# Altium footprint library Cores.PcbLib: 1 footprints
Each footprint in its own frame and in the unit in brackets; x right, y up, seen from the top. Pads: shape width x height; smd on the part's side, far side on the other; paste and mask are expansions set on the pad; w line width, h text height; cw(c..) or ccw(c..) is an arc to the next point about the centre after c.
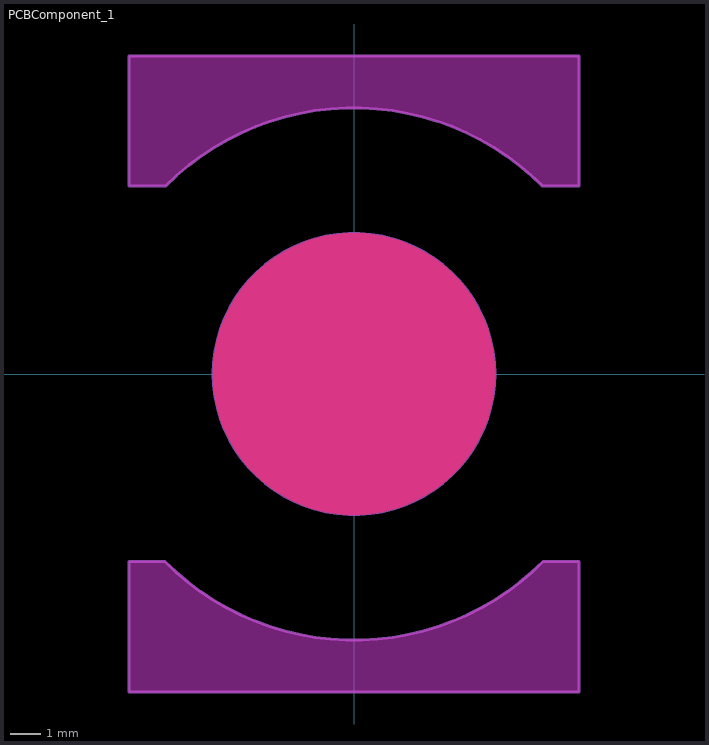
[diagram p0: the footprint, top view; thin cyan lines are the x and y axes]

## PCBComponent_1 [mm]
Top Layer:
  pour cut-out: 0,-4.6 -0.302,-4.6 -0.899,-4.521 -1.482,-4.365 -2.039,-4.134 -2.561,-3.833 -3.04,-3.466 -3.466,-3.04 -3.833,-2.561 -4.134,-2.039 -4.365,-1.482 -4.521,-0.899 -4.6,-0.302 -4.6,0 -4.6,0.301 -4.521,0.899 -4.365,1.482 -4.134,2.039 -3.833,2.561 -3.466,3.039 -3.04,3.466 -2.561,3.833 -2.039,4.134 -1.482,4.365 -0.899,4.521 -0.302,4.6 0,4.6 0.301,4.6 0.899,4.521 1.482,4.365 2.039,4.134 2.561,3.833 3.039,3.466 3.466,3.039 3.833,2.561 4.134,2.039 4.365,1.482 4.521,0.899 4.6,0.301 4.6,0 4.6,-0.302 4.521,-0.899 4.365,-1.482 4.134,-2.039 3.833,-2.561 3.466,-3.04 3.039,-3.466 2.561,-3.833 2.039,-4.134 1.482,-4.365 0.899,-4.521 0.301,-4.6
Keep-Out Layer:
  board cut-out: 0,-4.6 -0.302,-4.6 -0.899,-4.521 -1.482,-4.365 -2.039,-4.134 -2.561,-3.833 -3.04,-3.466 -3.466,-3.04 -3.833,-2.561 -4.134,-2.039 -4.365,-1.482 -4.521,-0.899 -4.6,-0.302 -4.6,0 -4.6,0.301 -4.521,0.899 -4.365,1.482 -4.134,2.039 -3.833,2.561 -3.466,3.039 -3.04,3.466 -2.561,3.833 -2.039,4.134 -1.482,4.365 -0.899,4.521 -0.302,4.6 0,4.6 0.301,4.6 0.899,4.521 1.482,4.365 2.039,4.134 2.561,3.833 3.039,3.466 3.466,3.039 3.833,2.561 4.134,2.039 4.365,1.482 4.521,0.899 4.6,0.301 4.6,0 4.6,-0.302 4.521,-0.899 4.365,-1.482 4.134,-2.039 3.833,-2.561 3.466,-3.04 3.039,-3.466 2.561,-3.833 2.039,-4.134 1.482,-4.365 0.899,-4.521 0.301,-4.6
  board cut-out: -7.35,-10.4 -7.35,-6.127 -6.176,-6.127 -5.867,-6.424 -5.205,-6.971 -4.493,-7.45 -3.737,-7.856 -2.945,-8.186 -2.125,-8.437 -1.283,-8.605 -0.429,-8.689 0.429,-8.689 1.283,-8.605 2.125,-8.437 2.945,-8.186 3.737,-7.856 4.493,-7.45 5.205,-6.971 5.867,-6.424 6.176,-6.127 7.35,-6.127 7.35,-10.4
  board cut-out: -7.348,6.152 -6.164,6.14 -5.855,6.435 -5.195,6.979 -4.485,7.455 -3.732,7.859 -2.943,8.187 -2.125,8.437 -1.287,8.604 -0.436,8.689 0.419,8.69 1.27,8.607 2.108,8.441 2.926,8.193 3.716,7.866 4.47,7.464 5.181,6.989 5.842,6.447 6.152,6.152 7.35,6.152 7.35,10.4 -7.35,10.4
M1 Board Outline:
  circle w0.1: c0,0 r4.6
  lines w0.1: -7.35,-10.4 -7.35,-6.127 -6.176,-6.127 ccw(c0,0) 6.176,-6.127 7.35,-6.127 7.35,-10.4 -7.35,-10.4 ; -7.35,10.4 7.35,10.4 7.35,6.152 6.152,6.152 ccw(c0,0) -6.164,6.14 -7.348,6.152 -7.35,10.4
M5 Assembly Top:
  text ".Designator" at -1.8,-0.514 h1.02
